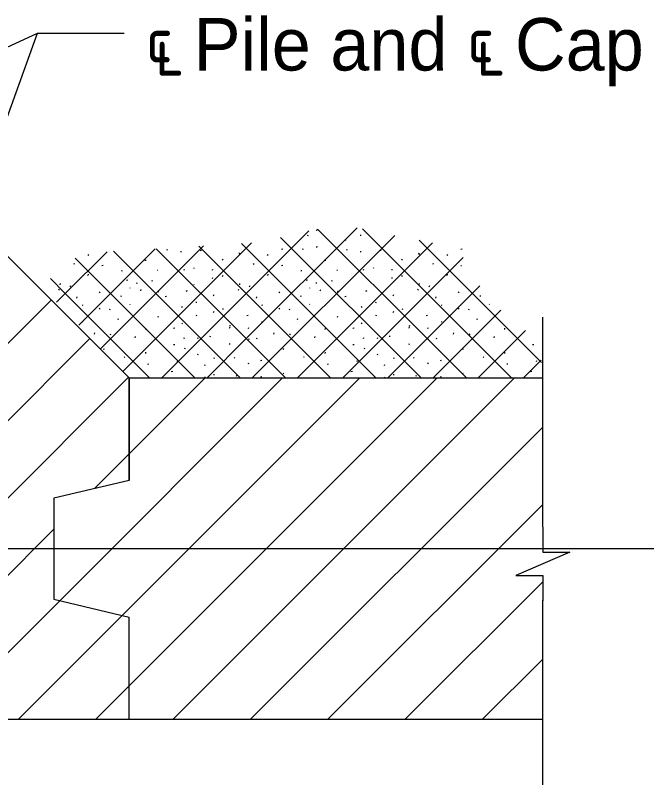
# Model space of a CAD drawing. Extents: x 111162.5 to 111216.6, y 110741.1 to 110776.1.
# Drawn here: x 111165.103 to 111166.922, y 110756.393 to 110758.59 of the extents above; entities that cross this region are included whole.
import ezdxf

# ---------------------------------------------------------------- set-up
doc = ezdxf.new("R2010")
doc.units = 0
for name, color, linetype in [('Patterning', 7, 'Continuous'), ('PlotBorder_dp', 7, 'Continuous'), ('SheetBorder_dp', 7, 'Continuous'), ('TextMisc', 7, 'Continuous')]:
    doc.layers.add(name, color=color, linetype=linetype)

msp = doc.modelspace()

# ---------------------------------------------------------------- linework, layer by layer
at = {"layer": 'Patterning'}
for p, q in [((111165.1667, 110758.537), (111163.9544, 110757.9846)), ((111165.1667, 110758.537), (111164.6302, 110757.0526)), ((111165.4165, 110758.537), (111165.1667, 110758.537)), ((111166.6224, 110757.1155), (111166.6224, 110757.7198)), ((111166.6224, 110756.3334), (111166.6224, 110756.9048))]:
    msp.add_line(p, q, dxfattribs=at)
msp.add_lwpolyline([(111166.6224, 110757.1152), (111166.6224, 110757.0427), (111166.6999, 110757.0427), (111166.6224, 110757.009), (111166.5449, 110756.9752), (111166.6224, 110756.9752), (111166.6224, 110756.9027)], dxfattribs=at)
at = {"layer": 'PlotBorder_dp'}
for p, q in [((111165.4309, 110757.5448), (111164.4466, 110758.5292)), ((111165.4309, 110757.2495), (111165.4309, 110757.5448)), ((111165.4309, 110757.5448), (111165.4309, 110757.2495)), ((111165.4309, 110757.5448), (111166.6224, 110757.5448)), ((111165.4309, 110757.2495), (111165.2144, 110757.1983)), ((111165.2144, 110757.1983), (111165.2144, 110756.9069)), ((111165.2144, 110756.9069), (111165.431, 110756.8557)), ((111165.4309, 110756.5605), (111165.4309, 110756.8558)), ((111165.431, 110756.5604), (111165.431, 110756.8557)), ((111165.4309, 110756.5605), (111163.4622, 110756.5605)), ((111166.6224, 110756.5605), (111165.4309, 110756.5605))]:
    msp.add_line(p, q, dxfattribs=at)
at = {"layer": 'TextMisc'}
for p, q in [((111165.7683, 110757.6579), (111166.0877, 110757.9774)), ((111165.7683, 110757.7881), (111165.9482, 110757.9681)), ((111165.9719, 110757.969), (111165.9726, 110757.972)), ((111166.2891, 110757.6579), (111165.9733, 110757.9738)), ((111166.2891, 110757.7881), (111166.103, 110757.9743)), ((111165.7858, 110757.5452), (111166.1961, 110757.9555)), ((111166.2719, 110757.545), (111165.8673, 110757.9496)), ((111165.9462, 110757.954), (111165.947, 110757.957)), ((111166.0982, 110757.954), (111166.0982, 110757.957)), ((111165.3496, 110757.6299), (111165.6451, 110757.9254)), ((111165.7683, 110757.7881), (111165.6319, 110757.9246)), ((111165.7683, 110757.9184), (111165.7546, 110757.9321)), ((111165.7683, 110757.9184), (111165.7838, 110757.9339)), ((111165.9719, 110757.9209), (111165.9726, 110757.9239)), ((111166.0538, 110757.9405), (111166.0553, 110757.9434)), ((111166.2891, 110757.9184), (111166.2662, 110757.9414)), ((111166.2891, 110757.9184), (111166.3044, 110757.9337)), ((111165.2475, 110757.7881), (111165.3677, 110757.9084)), ((111165.286, 110757.6964), (111165.5064, 110757.9169)), ((111165.3132, 110757.8975), (111165.3148, 110757.9006)), ((111165.7508, 110757.5452), (111165.3865, 110757.9095)), ((111165.4133, 110757.5633), (111165.7683, 110757.9184)), ((111165.7683, 110757.6579), (111165.5092, 110757.9171)), ((111165.5421, 110757.9134), (111165.5392, 110757.9127)), ((111165.5813, 110757.9066), (111165.5813, 110757.9096)), ((111165.6399, 110757.9119), (111165.6362, 110757.9111)), ((111165.7482, 110757.9021), (111165.7497, 110757.9051)), ((111165.7497, 110757.9006), (111165.7504, 110757.9036)), ((111166.1416, 110757.545), (111165.7683, 110757.9184)), ((111165.8301, 110757.8975), (111165.8317, 110757.9006)), ((111165.8736, 110757.9156), (111165.8698, 110757.9149)), ((111165.9159, 110757.5451), (111166.2891, 110757.9184)), ((111165.9327, 110757.9156), (111165.929, 110757.9149)), ((111166.059, 110757.9134), (111166.056, 110757.9127)), ((111166.0982, 110757.9066), (111166.0982, 110757.9096)), ((111166.1568, 110757.9119), (111166.1531, 110757.9111)), ((111166.2651, 110757.9021), (111166.2666, 110757.9051)), ((111166.2666, 110757.9006), (111166.2673, 110757.9036)), ((111166.6185, 110757.589), (111166.2891, 110757.9184)), ((111166.347, 110757.8975), (111166.3486, 110757.9006)), ((111166.3905, 110757.9156), (111166.3867, 110757.9149)), ((111165.6205, 110757.5453), (111165.2759, 110757.89)), ((111165.4805, 110757.8833), (111165.476, 110757.8833)), ((111165.6993, 110757.8841), (111165.7016, 110757.887)), ((111165.9974, 110757.8833), (111165.9929, 110757.8833)), ((111166.2162, 110757.8841), (111166.2185, 110757.887)), ((111166.2891, 110757.7881), (111166.3927, 110757.8917)), ((111165.2741, 110757.872), (111165.2726, 110757.8743)), ((111165.3567, 110757.8683), (111165.3529, 110757.8675)), ((111165.5895, 110757.8555), (111165.5903, 110757.8585)), ((111165.6188, 110757.86), (111165.6181, 110757.8615)), ((111165.6715, 110757.8555), (111165.6722, 110757.8585)), ((111165.791, 110757.872), (111165.7895, 110757.8743)), ((111165.8736, 110757.8683), (111165.8698, 110757.8675)), ((111166.1064, 110757.8555), (111166.1072, 110757.8585)), ((111166.1357, 110757.86), (111166.135, 110757.8615)), ((111166.1884, 110757.8555), (111166.1891, 110757.8585)), ((111166.3079, 110757.872), (111166.3064, 110757.8743)), ((111166.3878, 110757.8677), (111166.3867, 110757.8675)), ((111165.3125, 110757.8397), (111165.3118, 110757.8412)), ((111165.3156, 110757.8419), (111165.3125, 110757.8419)), ((111165.4102, 110757.8525), (111165.411, 110757.8555)), ((111165.5143, 110757.854), (111165.5129, 110757.8547)), ((111165.6715, 110757.8314), (111165.6722, 110757.8344)), ((111165.6993, 110757.8367), (111165.7016, 110757.8397)), ((111165.8294, 110757.8397), (111165.8287, 110757.8412)), ((111165.8324, 110757.8419), (111165.8294, 110757.8419)), ((111165.9271, 110757.8525), (111165.9279, 110757.8555)), ((111166.0312, 110757.854), (111166.0297, 110757.8547)), ((111166.1884, 110757.8314), (111166.1891, 110757.8344)), ((111166.2162, 110757.8367), (111166.2185, 110757.8397)), ((111166.3463, 110757.8397), (111166.3456, 110757.8412)), ((111166.3493, 110757.8419), (111166.3463, 110757.8419)), ((111165.2475, 110757.7881), (111165.2049, 110757.8308)), ((111165.2328, 110757.8134), (111165.2335, 110757.8164)), ((111165.4279, 110757.8261), (111165.4241, 110757.8254)), ((111165.4534, 110757.8171), (111165.4542, 110757.8201)), ((111165.4978, 110757.8239), (111165.4985, 110757.8268)), ((111165.6188, 110757.8127), (111165.6181, 110757.8142)), ((111165.7497, 110757.8134), (111165.7504, 110757.8164)), ((111165.9448, 110757.8261), (111165.941, 110757.8254)), ((111165.9703, 110757.8171), (111165.9711, 110757.8201)), ((111166.0147, 110757.8239), (111166.0154, 110757.8268)), ((111166.1357, 110757.8127), (111166.135, 110757.8142)), ((111166.2666, 110757.8134), (111166.2673, 110757.8164)), ((111165.2291, 110757.7976), (111165.2305, 110757.8006)), ((111165.2614, 110757.8073), (111165.2629, 110757.8111)), ((111165.3463, 110757.7901), (111165.3478, 110757.7931)), ((111165.4347, 110757.8036), (111165.4342, 110757.8044)), ((111165.4647, 110757.7953), (111165.4662, 110757.7991)), ((111165.5151, 110757.7923), (111165.5166, 110757.7953)), ((111165.5985, 110757.7953), (111165.5948, 110757.7938)), ((111165.746, 110757.7976), (111165.7474, 110757.8006)), ((111165.7783, 110757.8073), (111165.7798, 110757.8111)), ((111165.8632, 110757.7901), (111165.8647, 110757.7931)), ((111165.9516, 110757.8036), (111165.9511, 110757.8044)), ((111165.9816, 110757.7953), (111165.9831, 110757.7991)), ((111166.032, 110757.7923), (111166.0335, 110757.7953)), ((111166.1154, 110757.7953), (111166.1117, 110757.7938)), ((111166.2629, 110757.7976), (111166.2643, 110757.8006)), ((111166.2891, 110757.6579), (111166.4408, 110757.8097)), ((111166.2952, 110757.8073), (111166.2967, 110757.8111)), ((111166.3801, 110757.7901), (111166.3816, 110757.7931)), ((111163.9979, 110756.5605), (111165.2066, 110757.7692)), ((111165.2223, 110757.763), (111165.2475, 110757.7882)), ((111165.4903, 110757.5453), (111165.2475, 110757.7882)), ((111165.2809, 110757.775), (111165.2817, 110757.778)), ((111165.4087, 110757.7795), (111165.4094, 110757.7826)), ((111165.5255, 110757.5453), (111165.7683, 110757.7882)), ((111165.5392, 110757.7795), (111165.5354, 110757.7788)), ((111165.6745, 110757.781), (111165.6761, 110757.7847)), ((111166.0114, 110757.5451), (111165.7683, 110757.7882)), ((111165.7978, 110757.775), (111165.7986, 110757.778)), ((111165.9256, 110757.7795), (111165.9263, 110757.7826)), ((111166.0461, 110757.5451), (111166.2891, 110757.7882)), ((111166.056, 110757.7795), (111166.0523, 110757.7788)), ((111166.1914, 110757.781), (111166.193, 110757.7847)), ((111166.5324, 110757.5448), (111166.2891, 110757.7882)), ((111166.3147, 110757.775), (111166.3155, 110757.778)), ((111166.4425, 110757.7795), (111166.4432, 110757.7826)), ((111165.299, 110757.7532), (111165.2967, 110757.754)), ((111165.4347, 110757.7562), (111165.4339, 110757.7577)), ((111165.5851, 110757.748), (111165.5828, 110757.7502)), ((111165.6249, 110757.7608), (111165.6257, 110757.7637)), ((111165.8159, 110757.7532), (111165.8136, 110757.754)), ((111165.9516, 110757.7562), (111165.9508, 110757.7577)), ((111166.1019, 110757.748), (111166.0997, 110757.7502)), ((111166.1418, 110757.7608), (111166.1426, 110757.7637)), ((111166.3328, 110757.7532), (111166.3305, 110757.754)), ((111166.4685, 110757.7562), (111166.4677, 110757.7577)), ((111165.3463, 110757.7427), (111165.3478, 110757.7457)), ((111165.3758, 110757.741), (111165.3766, 110757.7441)), ((111165.6257, 110757.7239), (111165.6264, 110757.7269)), ((111165.6745, 110757.7336), (111165.6761, 110757.7374)), ((111165.7016, 110757.742), (111165.7023, 110757.7449)), ((111165.7738, 110757.7246), (111165.7699, 110757.7239)), ((111165.8632, 110757.7427), (111165.8647, 110757.7457)), ((111165.8927, 110757.741), (111165.8935, 110757.7441)), ((111166.1426, 110757.7239), (111166.1433, 110757.7269)), ((111166.1914, 110757.7336), (111166.193, 110757.7374)), ((111166.2185, 110757.742), (111166.2192, 110757.7449)), ((111166.2907, 110757.7246), (111166.2868, 110757.7239)), ((111166.3064, 110757.5449), (111166.5015, 110757.7401)), ((111166.3801, 110757.7427), (111166.3816, 110757.7457)), ((111166.4096, 110757.741), (111166.4104, 110757.7441)), ((111165.299, 110757.7058), (111165.2967, 110757.7066)), ((111165.3996, 110757.7127), (111165.4004, 110757.7157)), ((111165.5147, 110757.7197), (111165.5155, 110757.7226)), ((111165.5851, 110757.7006), (111165.5828, 110757.7028)), ((111165.8159, 110757.7058), (111165.8136, 110757.7066)), ((111165.9165, 110757.7127), (111165.9172, 110757.7157)), ((111166.0316, 110757.7197), (111166.0323, 110757.7226)), ((111166.1019, 110757.7006), (111166.0997, 110757.7028)), ((111166.3328, 110757.7058), (111166.3305, 110757.7066)), ((111166.4334, 110757.7127), (111166.4341, 110757.7157)), ((111165.479, 110757.6847), (111165.4797, 110757.6878)), ((111165.5625, 110757.6878), (111165.5587, 110757.687)), ((111165.7203, 110757.6885), (111165.7219, 110757.6916)), ((111165.7219, 110757.6938), (111165.7226, 110757.6969)), ((111165.7748, 110757.6868), (111165.7756, 110757.6898)), ((111165.9959, 110757.6847), (111165.9966, 110757.6878)), ((111166.0794, 110757.6878), (111166.0756, 110757.687)), ((111166.2372, 110757.6885), (111166.2388, 110757.6916)), ((111166.2388, 110757.6938), (111166.2395, 110757.6969)), ((111166.2917, 110757.6868), (111166.2925, 110757.6898)), ((111166.4365, 110757.5449), (111166.573, 110757.6814)), ((111166.5128, 110757.6847), (111166.5135, 110757.6878)), ((111165.3313, 110757.6713), (111165.3321, 110757.6743)), ((111165.3775, 110757.6691), (111165.379, 110757.6721)), ((111165.4489, 110757.6607), (111165.4496, 110757.6637)), ((111165.5895, 110757.6584), (111165.5903, 110757.6615)), ((111165.6294, 110757.6584), (111165.6301, 110757.6615)), ((111165.6647, 110757.6634), (111165.6655, 110757.6663)), ((111165.7993, 110757.6577), (111165.8, 110757.6607)), ((111165.8482, 110757.6713), (111165.849, 110757.6743)), ((111165.8944, 110757.6691), (111165.8959, 110757.6721)), ((111165.9658, 110757.6607), (111165.9665, 110757.6637)), ((111166.1064, 110757.6584), (111166.1072, 110757.6615)), ((111166.1463, 110757.6584), (111166.147, 110757.6615)), ((111166.1816, 110757.6634), (111166.1823, 110757.6663)), ((111166.3162, 110757.6577), (111166.3169, 110757.6607)), ((111166.3651, 110757.6713), (111166.3659, 110757.6743)), ((111166.4113, 110757.6691), (111166.4128, 110757.6721)), ((111166.4827, 110757.6607), (111166.4834, 110757.6637)), ((111164.2206, 110756.5605), (111165.318, 110757.6579)), ((111165.5625, 110757.6405), (111165.5587, 110757.6397)), ((111165.6556, 110757.5452), (111165.7683, 110757.6579)), ((111165.7203, 110757.6412), (111165.7219, 110757.6442)), ((111165.8811, 110757.5451), (111165.7683, 110757.6579)), ((111165.7768, 110757.6562), (111165.7738, 110757.6555)), ((111166.0794, 110757.6405), (111166.0756, 110757.6397)), ((111166.1762, 110757.545), (111166.2891, 110757.6579)), ((111166.2372, 110757.6412), (111166.2388, 110757.6442)), ((111166.4022, 110757.5449), (111166.2891, 110757.6579)), ((111166.2937, 110757.6562), (111166.2907, 110757.6555)), ((111166.5962, 110757.6405), (111166.5925, 110757.6397)), ((111165.3581, 110757.6269), (111165.3595, 110757.6299)), ((111165.479, 110757.6156), (111165.4797, 110757.6186)), ((111165.592, 110757.6282), (111165.5928, 110757.6312)), ((111165.875, 110757.6269), (111165.8764, 110757.6299)), ((111165.9959, 110757.6156), (111165.9966, 110757.6186)), ((111166.1089, 110757.6282), (111166.1097, 110757.6312)), ((111166.3919, 110757.6269), (111166.3933, 110757.6299)), ((111166.5128, 110757.6156), (111166.5135, 110757.6186)), ((111165.4188, 110757.6036), (111165.4173, 110757.6058)), ((111165.5707, 110757.5916), (111165.5715, 110757.5945)), ((111165.6294, 110757.6111), (111165.6301, 110757.6141)), ((111165.6775, 110757.6014), (111165.6745, 110757.6006)), ((111165.7354, 110757.6014), (111165.7332, 110757.6036)), ((111165.8129, 110757.5953), (111165.8099, 110757.5938)), ((111165.9357, 110757.6036), (111165.9342, 110757.6058)), ((111166.0876, 110757.5916), (111166.0884, 110757.5945)), ((111166.1463, 110757.6111), (111166.147, 110757.6141)), ((111166.1944, 110757.6014), (111166.1914, 110757.6006)), ((111166.2523, 110757.6014), (111166.2501, 110757.6036)), ((111166.3297, 110757.5953), (111166.3268, 110757.5938)), ((111166.4526, 110757.6036), (111166.4511, 110757.6058)), ((111166.5666, 110757.5448), (111166.6179, 110757.596)), ((111166.6045, 110757.5916), (111166.6053, 110757.5945)), ((111165.4865, 110757.5836), (111165.4873, 110757.5866)), ((111165.6496, 110757.5803), (111165.6504, 110757.5833)), ((111165.7745, 110757.5855), (111165.7761, 110757.5885)), ((111166.0034, 110757.5836), (111166.0042, 110757.5866)), ((111166.1665, 110757.5803), (111166.1673, 110757.5833)), ((111166.2914, 110757.5855), (111166.293, 110757.5885)), ((111166.5203, 110757.5836), (111166.5211, 110757.5866)), ((111165.5572, 110757.5629), (111165.5527, 110757.5622)), ((111165.6775, 110757.554), (111165.6745, 110757.5532)), ((111165.7407, 110757.5495), (111165.7414, 110757.5525)), ((111165.8766, 110757.5562), (111165.8751, 110757.5584)), ((111166.0741, 110757.5629), (111166.0696, 110757.5622)), ((111166.1944, 110757.554), (111166.1914, 110757.5532)), ((111166.2575, 110757.5495), (111166.2583, 110757.5525)), ((111166.3935, 110757.5562), (111166.392, 110757.5584)), ((111166.591, 110757.5629), (111166.5865, 110757.5622)), ((111164.4433, 110756.5605), (111165.4293, 110757.5465)), ((111165.2313, 110756.9029), (111165.8732, 110757.5448)), ((111165.3316, 110757.226), (111165.6504, 110757.5448)), ((111165.3343, 110756.5605), (111166.3186, 110757.5448)), ((111165.4115, 110756.8604), (111166.0959, 110757.5448)), ((111165.557, 110756.5605), (111166.5413, 110757.5448)), ((111165.6497, 110757.5453), (111165.6504, 110757.5479)), ((111165.8129, 110757.5479), (111165.8099, 110757.5465)), ((111166.1666, 110757.545), (111166.1673, 110757.5479)), ((111166.3297, 110757.5479), (111166.3268, 110757.5465)), ((111165.7797, 110756.5605), (111166.6224, 110757.4031)), ((111166.0024, 110756.5605), (111166.6224, 110757.1804)), ((111164.666, 110756.5605), (111165.2144, 110757.1088)), ((111166.6224, 110757.0526), (111162.9802, 110757.0526)), ((111167.0161, 110757.0526), (111166.6224, 110757.0526)), ((111166.2252, 110756.5605), (111166.6224, 110756.9577)), ((111164.8888, 110756.5605), (111165.2313, 110756.903)), ((111165.1115, 110756.5605), (111165.4115, 110756.8604)), ((111166.448, 110756.5605), (111166.6224, 110756.7349))]:
    msp.add_line(p, q, dxfattribs=at)

# ---------------------------------------------------------------- texts
at = {"layer": 'SheetBorder_dp'}
msp.add_text('℄ Pile and ℄ Cap', height=0.1512, dxfattribs=at).set_placement((111165.4791, 110758.4304))

doc.saveas('drawing.dxf')
